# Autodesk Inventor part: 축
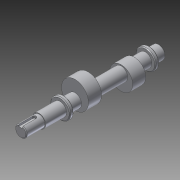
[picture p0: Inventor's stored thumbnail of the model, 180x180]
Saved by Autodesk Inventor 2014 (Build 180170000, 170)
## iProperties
Created: 2014-12
Part Number: 축
Material: 알루미늄 6061
Document SubType Name: Modeling
Designer: Owner
Density: 2.71 g/cm^3
Appearance: 알루미늄 - 평지
Mass: 170.354 g
Surface Area: 153.402 cm^2
Volume: 62.8614 cm^3
Author: Owner
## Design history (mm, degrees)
sketch "스케치1"
  geometry: L1 (-90, 0)-(90, 0); L2 (-90, 0)-(-90, 7.5); L3 (-90, 7.5)-(-66, 7.5); L4 (-66, 7.5)-(-66, 8.5); L5 (-66, 8.5)-(-39, 8.5); L6 (-39, 8.5)-(-39, 13); L7 (-39, 13)-(-34, 13); L8 (-34, 13)-(-34, 8.5); L9 (-34, 8.5)-(72, 8.5); L10 (72, 8.5)-(72, 13); L11 (72, 13)-(77, 13); L12 (77, 13)-(77, 8.5); L13 (77, 8.5)-(90, 8.5); L14 (90, 8.5)-(90, 0); 4 further points
  constraints: 28 end point, 6 parallel, 5 perpendicular, 3 midpoint, 3 point on line, 2 horizontal, 1 coincident, 1 horizontal alignment
  dimensions: "d0" = 180 distance of L1.start L1.end; "d1" = 24 distance of L2.end L3.end; "d2" = 27 distance of L4.end L5.end; "d3" = 5 distance of L6.end L7.end; "d4" = 5 distance of L10.end L11.end; "d5" = 13 distance of L12.end L13.end; "d6" = 15 diameter of L3 L1; "d7" = 17 diameter of L5 L1; "d8" = 26 diameter of L7 L1
revolve "회전1" sketch "스케치1" stored, may be unused: angle "d9" = 90 deg
node "작업 평면1"
sketch "스케치2"
  geometry: 1 further point
sketch "스케치3"
  geometry: C1 r 17.5 at (0, 6); 1 further point
  constraints: 1 centre point, 1 vertical alignment
  dimensions: "d11" = 35 diameter of C1; "d12" = 6 distance of point (0, 0) C1.centre
extrude "돌출1" join sketch "스케치3" distance "d13" = 17; taper "d14" = 0 deg
node "작업 평면2"
sketch "스케치4"
  geometry: C1 r 15 at (0, -5); 1 further point
  constraints: 1 centre point, 1 vertical alignment
  dimensions: "d16" = 30 diameter of C1; "d17" = 5 distance of C1.centre point (0, 0)
extrude "돌출2" join sketch "스케치4" distance "d18" = 17; taper "d19" = 0 deg
node "작업 평면3"
sketch "스케치5"
  geometry: L1 (0, 5.5)-(0, -12); L2 (-2.5, 5.5)-(-2.5, -12); L3 (2.5, -12)-(2.5, 5.5); L4 (7.5, -12)-(-7.5, -12) reference; A1 r 2.5 centre (0, 5.5) between (2.5, 5.5) and (-2.5, 5.5); A2 r 2.5 centre (0, -12) between (-2.5, -12) and (2.5, -12); 3 further points
  constraints: 8 end point, 4 point on circle, 4 tangent, 2 centre point, 2 midpoint, 1 parallel, 1 point on line, 1 vertical, 1 vertical alignment
  dimensions: "d28" = 5 distance between parallel lines of L3 L2; "d29" = 20 dimension on A1 L4
extrude "돌출3" cut sketch "스케치5" distance "d22" = 3; taper "d23" = 0 deg
chamfer "모따기1" distance "d24" = 1; stored, may be unused: second distance "d25" = 2, angle "d26" = 45 deg
node "솔리드1"
other parameters: "d10" = -19.5, "d15" = 40.5
